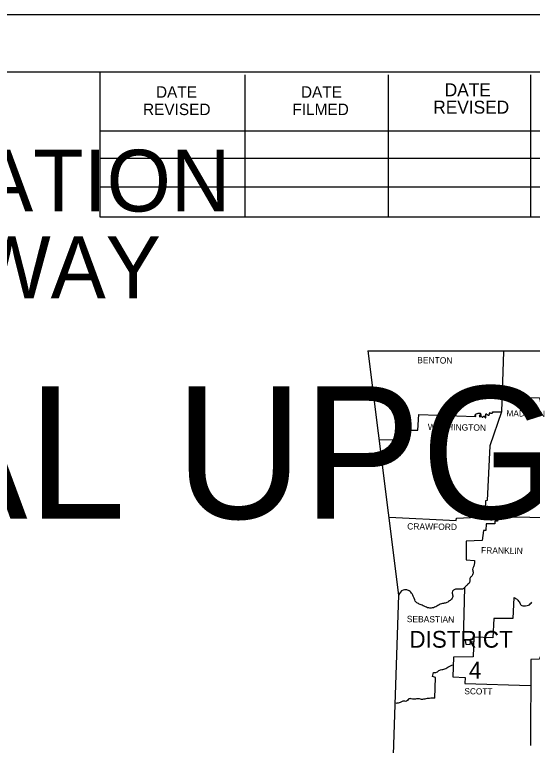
# Model space of a CAD drawing. Extents: x 19118 to 454486, y 1325406 to 1693506.
# Drawn here: x 26164.9 to 26517, y 1327042.2 to 1327539.3 of the extents above; entities that cross this region are included whole.
import ezdxf

# ---------------------------------------------------------------- set-up
doc = ezdxf.new("R2010")
doc.units = 0
for name, color, linetype in [('S_CURB', 7, 'Continuous'), ('S_EDGE_PAVEMENT', 7, 'Continuous'), ('S_SHOULDER', 7, 'Continuous')]:
    doc.layers.add(name, color=color, linetype=linetype)

msp = doc.modelspace()

# ---------------------------------------------------------------- linework, layer by layer
at = {"layer": 'S_CURB'}
for points in [[(26405.17, 1327310.68), (26566.87, 1327310.58), (26708.77, 1327310.88), (26876.16, 1327313.48), (26953.76, 1327315.28)], [(26405.17, 1327310.68), (26425.87, 1327144.48), (26416.87, 1326873.19)], [(26497.47, 1327310.08), (26496.07, 1327269.08)], [(26496.42, 1327279.51), (26521.87, 1327278.68), (26522.47, 1327275.48), (26525.87, 1327275.38), (26525.77, 1327273.38), (26528.17, 1327272.78), (26528.37, 1327261.88), (26531.47, 1327261.18), (26531.67, 1327256.88), (26536.07, 1327256.28), (26536.27, 1327252.28), (26544.97, 1327251.38), (26567.37, 1327251.88), (26567.57, 1327310.58)], [(26413.07, 1327250.18), (26431.77, 1327250.08), (26432.27, 1327256.68), (26439.17, 1327256.68), (26439.77, 1327267.38), (26478.46, 1327266)], [(26489.89, 1327269.05), (26496.07, 1327269.08), (26487.97, 1327245.88), (26486.37, 1327208.78), (26485.17, 1327208.68), (26484.57, 1327197.48), (26490.47, 1327196.98), (26491.37, 1327197.88), (26539.07, 1327196.98), (26539.57, 1327191.68)], [(26419.67, 1327197.38), (26465.17, 1327195.28), (26465.37, 1327196.88), (26484.37, 1327197.78)], [(26493.37, 1327197.85), (26493.37, 1327194.78), (26491.47, 1327194.78), (26491.57, 1327192.98), (26485.47, 1327192.88), (26485.37, 1327188.38), (26483.67, 1327188.38), (26482.77, 1327181.68), (26471.97, 1327181.18), (26471.87, 1327168.48), (26477.67, 1327168.08)], [(26470.9, 1327149.56), (26469.87, 1327113.88), (26471.37, 1327113.48), (26471.67, 1327111.08), (26474.67, 1327110.88), (26474.97, 1327112.58), (26477.37, 1327112.98)], [(26504.47, 1327142.88), (26503.77, 1327128.58), (26490.77, 1327128.48), (26490.07, 1327115.48), (26477.17, 1327115.78), (26476.77, 1327102.38), (26463.27, 1327102.28), (26462.87, 1327088.88), (26471.37, 1327088.38), (26471.07, 1327084.28), (26515.81, 1327083.05)], [(26570.17, 1327127.58), (26569.77, 1327113.18), (26546.97, 1327113.08), (26543.97, 1327110.48), (26542.27, 1327106.48), (26539.77, 1327106.68), (26539.67, 1327104.38), (26536.77, 1327104.08), (26536.87, 1327101.98), (26522.37, 1327102.38), (26521.87, 1327100.78), (26515.87, 1327100.58), (26515.67, 1327042.23)], [(26450.77, 1327074.38), (26451.07, 1327088.48), (26449.07, 1327089.08), (26449.67, 1327091.78)]]:
    msp.add_lwpolyline(points, dxfattribs=at)
for centre, radius, start, end in [((26478.02, 1327266.72), 0.176, 156.045, 216.8602), ((26478.1, 1327266.68), 0.263, 125.5472, 156.045), ((26478.38, 1327266.99), 0.62, 216.8602, 248.1917), ((26482.64, 1327263.22), 5.97, 135.8747, 141.9374), ((26478.19, 1327266.52), 0.113, 248.1917, 347.1581), ((26478.41, 1327266.46), 0.113, 39.7957, 167.1581), ((26481, 1327262.26), 5.76, 111.5873, 117.3149), ((26478.41, 1327266.22), 0.196, 286.231, 356.4249), ((26478.13, 1327266.23), 0.473, 356.4249, 39.7957), ((26480.16, 1327264.23), 3.61, 102.7546, 110.6543), ((26483.1, 1327247.69), 20.41, 96.7932, 100.5516), ((26481.08, 1327266.13), 1.87, 89.3336, 102.0989), ((26481.55, 1327266.29), 0.631, 132.41, 167.3343), ((26482.73, 1327266.76), 1.82, 190.4879, 208.8781), ((26481.08, 1327266.38), 1.62, 66.564, 89.3336), ((26481.38, 1327266.65), 0.273, 68.1414, 155.5454), ((26481.36, 1327266.15), 0.349, 229.2667, 280.0802), ((26481.48, 1327266.12), 0.322, 259.6916, 298.8193), ((26481.58, 1327267.15), 0.273, 248.0969, 311.8879), ((26481.52, 1327266.05), 0.247, 298.8193, 356.0222), ((26481.43, 1327267.19), 0.734, 32.4621, 66.564), ((26480.94, 1327267.87), 1.24, 311.8879, 335.7798), ((26482.01, 1327266.02), 0.247, 110.8612, 176.0222), ((26481.96, 1327266.14), 0.114, 67.373, 110.8612), ((26481.31, 1327264.59), 1.8, 56.6801, 67.373), ((26481.85, 1327267.46), 0.235, 335.7798, 32.4621), ((26481.9, 1327265.48), 0.733, 31.4192, 56.6801), ((26483.11, 1327265.97), 0.593, 190.5048, 239.8098), ((26482.96, 1327266.35), 0.904, 260.462, 312.7214), ((26484.01, 1327265.22), 0.641, 103.7654, 132.9836), ((26484.78, 1327262.1), 3.85, 94.9715, 103.7654), ((26484.46, 1327265.68), 0.251, 60.0097, 94.9715), ((26484.47, 1327265.69), 0.248, 333.5484, 60.0097), ((26484.97, 1327265.58), 0.285, 181.1358, 232.5966), ((26486.21, 1327266.01), 1.56, 205.0092, 220.2264), ((26485.83, 1327267), 0.734, 133.169, 186.7209), ((26486.69, 1327267.11), 1.6, 186.725, 211.1186), ((26485.61, 1327267.06), 0.561, 84.2874, 120.9726), ((26482.94, 1327265.47), 2.51, 356.1873, 18.9181), ((26485.08, 1327265.32), 0.372, 310.2463, 356.1873), ((26485.63, 1327267.26), 0.354, 25.1247, 84.2874), ((26486.2, 1327267.6), 0.302, 217.103, 260.4946), ((26491.04, 1327274.04), 8.33, 234.0433, 240.9011), ((26487.05, 1327267), 0.246, 254.84, 285.5846), ((26487.21, 1327267.16), 0.405, 255.9788, 27.04), ((26487.79, 1327267.47), 0.256, 131.9339, 211.1431), ((26488.43, 1327267.81), 0.819, 165.762, 190.3593), ((26488.26, 1327268.03), 0.623, 152.9692, 181.5409), ((26488.09, 1327266.87), 1.49, 70.6596, 104.9036), ((26489.43, 1327270.05), 1.96, 244.3985, 264.9644), ((26489.22, 1327269.95), 1.85, 271.1237, 284.041), ((26489.63, 1327268.29), 0.151, 284.041, 330.4698), ((26489.14, 1327269.06), 1.05, 306.5402, 333.8685), ((26489.42, 1327268.49), 0.67, 9.5116, 55.9405), ((26485.1, 1327264.99), 0.0792, 169.0691, 214.0773), ((26485.07, 1327265.33), 0.387, 265.2347, 310.2463)]:
    msp.add_arc(centre, radius, start, end, dxfattribs=at)
for points in [[(26477.67, 1327168.08), (26477.67, 1327165.98), (26476.87, 1327163.78), (26476.37, 1327161.88), (26476.67, 1327159.38), (26475.77, 1327157.38), (26474.47, 1327155.78), (26474.47, 1327153.78), (26472.97, 1327151.68), (26471.37, 1327150.08), (26469.97, 1327148.78), (26467.47, 1327148.58), (26465.37, 1327148.48), (26463.27, 1327147.78), (26462.47, 1327146.28), (26462.87, 1327143.98), (26462.07, 1327141.78), (26459.97, 1327140.08), (26457.67, 1327138.98), (26455.27, 1327138.58), (26451.97, 1327136.98), (26448.97, 1327135.68), (26445.77, 1327135.88), (26442.77, 1327137.18), (26440.07, 1327138.38), (26437.97, 1327139.58), (26436.27, 1327143.28), (26435.17, 1327145.28), (26433.27, 1327147.28), (26430.97, 1327148.08), (26429.07, 1327147.88), (26425.87, 1327144.48)], [(26504.47, 1327142.88), (26506.67, 1327141.48), (26508.37, 1327139.18), (26509.87, 1327137.28), (26512.37, 1327137.18), (26514.37, 1327137.58), (26516.67, 1327139.58)], [(26449.67, 1327091.78), (26451.87, 1327091.98), (26453.97, 1327093.38), (26456.77, 1327093.98), (26459.57, 1327095.48), (26463.07, 1327097.08)], [(26450.77, 1327074.38), (26447.87, 1327074.28), (26444.57, 1327073.88), (26441.57, 1327073.48), (26438.87, 1327073.98), (26436.37, 1327073.58), (26434.67, 1327073.98), (26432.57, 1327073.48), (26431.37, 1327072.28), (26428.87, 1327072.28), (26427.07, 1327071.48), (26424.17, 1327070.78)]]:
    msp.add_spline(points, degree=3, dxfattribs=at)
at = {"layer": 'S_EDGE_PAVEMENT'}
msp.add_lwpolyline([(23759.74, 1327539.29), (27093.14, 1327539.29), (27093.14, 1325405.92), (23759.74, 1325405.92)], close=True, dxfattribs=at)
at = {"layer": 'S_SHOULDER'}
for p, q in [((23883.81, 1327500.35), (27045.61, 1327500.35)), ((26223.01, 1327401.55), (26223.01, 1327500.35)), ((26321.61, 1327401.55), (26321.61, 1327498.35)), ((26419.21, 1327401.55), (26419.21, 1327498.35)), ((26516.01, 1327401.55), (26516.01, 1327498.35)), ((26223.01, 1327460.15), (26614.61, 1327460.15)), ((26223.01, 1327441.55), (26614.61, 1327441.55)), ((26223.01, 1327401.55), (26223.01, 1327422.15)), ((26223.01, 1327422.15), (26614.61, 1327422.15)), ((27045.61, 1327401.55), (26223.01, 1327401.55))]:
    msp.add_line(p, q, dxfattribs=at)

# ---------------------------------------------------------------- texts
at = {"layer": 'S_CURB'}
for s, height, p in [('ARKANSAS DEPARTMENT OF TRANSPORTATION', 42, (24976.11, 1327405.38)), ('CONSTRUCTION PLANS FOR STATE HIGHWAY', 42, (24997.41, 1327346.38)), ('MAIN ST.   SPRUCE ST. SIGNAL UPGRADE', 89.9998, (24421.67, 1327196.45)), ('DISTRICT', 11.4, (26433.37, 1327108.68)), ('4', 11.4, (26473.87, 1327087.68))]:
    msp.add_text(s, height=height, dxfattribs=at).set_placement(p)
for s, height, rotation, p in [('BENTON', 4.301, 359.2527, (26438.67, 1327302.18)), ('MADISON', 4.201, 359.0906, (26499.37, 1327266.08)), ('WASHINGTON', 4.3, 359.232, (26445.87, 1327256.68)), ('CRAWFORD', 4.299, 359.2771, (26431.87, 1327189.08)), ('FRANKLIN', 4.301, 359.1815, (26482.07, 1327172.78)), ('SEBASTIAN', 4.299, 359.2816, (26431.57, 1327126.08)), ('SCOTT', 4.201, 359.4063, (26470.77, 1327076.98))]:
    msp.add_text(s, height=height, rotation=rotation, dxfattribs=at).set_placement(p)
at = {"layer": 'S_SHOULDER'}
for s, height, p in [('DATE', 7.819, (26261.01, 1327482.75)), ('DATE', 7.819, (26359.61, 1327482.75)), ('DATE', 8.792, (26457.41, 1327483.75)), ('REVISED', 7.819, (26252.21, 1327470.95)), ('REVISED', 8.792, (26449.61, 1327471.95)), ('FILMED', 7.819, (26353.81, 1327470.95))]:
    msp.add_text(s, height=height, dxfattribs=at).set_placement(p)

doc.saveas('drawing.dxf')
